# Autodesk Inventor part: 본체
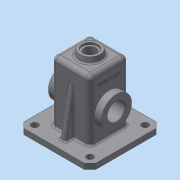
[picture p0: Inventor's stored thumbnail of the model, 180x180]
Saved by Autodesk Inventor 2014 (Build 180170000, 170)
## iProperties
Created: 2016-02
Part Number: 본체
Material: 일반
Document SubType Name: Modeling
Designer: 406-강의용
Density: 1 g/cm^3
Appearance: 기본값
Author: 406-강의용
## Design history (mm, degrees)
sketch "스케치1"
  geometry: L1 (-65, 0)-(65, 0); L2 (65, 0)-(65, 10); L3 (65, 10)-(-65, 10); L4 (-65, 10)-(-65, 0); 2 further points
  constraints: 8 end point, 2 parallel, 1 coincident, 1 horizontal, 1 midpoint, 1 perpendicular
  dimensions: "d0" = 130 distance between parallel lines of L4 L2; "d1" = 10 distance between parallel lines of L1 L3
extrude "돌출1" new body sketch "스케치1" distance "d2" = 130; taper "d3" = 0 deg
sketch "스케치2"
  geometry: L1 (130, 0)-(0, 0) reference; L2 (130, 0)-(130, -130) reference; L3 (30, -100)-(100, -100); L4 (100, -100)-(100, -30); L5 (100, -30)-(30, -30); L6 (30, -30)-(30, -100); 5 further points
  constraints: 8 end point, 4 midpoint, 2 parallel, 1 horizontal, 1 horizontal alignment, 1 perpendicular, 1 vertical alignment
  dimensions: "d4" = 70 distance between parallel lines of L3 L5; "d5" = 70 distance between parallel lines of L6 L4
extrude "돌출2" join sketch "스케치2" distance "d6" = 110; taper "d7" = 0 deg
sketch "스케치3"
  geometry: L1 (35, 35)-(95, 35); L2 (95, 35)-(95, 95); L3 (95, 95)-(35, 95); L4 (35, 95)-(35, 35); L5 (100, 100)-(30, 100) reference; L6 (100, 30)-(100, 100) reference; L7 (30, 30)-(100, 30) reference; 1 further point
  constraints: 8 end point, 2 parallel, 2 perpendicular, 1 horizontal
  dimensions: "d8" = 5 distance between parallel lines of L5 L3; "d9" = 5 distance between parallel lines of L6 L2; "d10" = 5 distance between parallel lines of L7 L1
extrude "돌출3" cut sketch "스케치3" distance "d11" = 115; taper "d12" = 0 deg
fillet "모깎기1" dims "d13" = 8
fillet "모깎기2" dims "d14" = 8
chamfer "모따기1" distance "d15" = 10; stored, may be unused: second distance "d16" = 2, angle "d17" = 45 deg
node "작업 평면1"
sketch "스케치4"
  geometry: L1 (90, 112)-(90, 10) reference; L2 (90, 10)-(120, 10) reference; L3 (120, 10)-(120, 0) reference; L4 (120, 0)-(85, 0) reference; L5 (85, 0)-(85, 115) reference; L6 (85, 115)-(25, 115) reference; L7 (25, 115)-(25, 0) reference; L8 (25, 0)-(-10, 0) reference; L9 (-10, 0)-(-10, 10) reference; L10 (-10, 10)-(20, 10) reference; L11 (20, 10)-(20, 112) reference; L12 (28, 120)-(82, 120) reference; L13 (105, 10)-(90, 95.069); A1 r 8 centre (82, 112) between (90, 112) and (82, 120) reference; A2 r 8 centre (28, 112) between (28, 120) and (20, 112) reference
  constraints: 2 end point, 1 midpoint, 1 point on line
  dimensions: "d18" = 100 deg angle of L2 L13; "d19" = 15 distance from line of L3 L13.start
extrude "돌출4" join sketch "스케치4" stored distance "d20" = 10; taper "d21" = 0 deg
fillet "모깎기3" dims "d22" = 3
fillet "모깎기4" dims "d23" = 3
node "작업 평면2"
fillet "모깎기5" dims "d24" = 3
node "작업 평면3"
sketch "스케치6"
  geometry: L1 (62, 0)-(62, -99) reference; L2 (65, -102)-(92, -102) reference; L3 (92, -102)-(92, -112) reference; L4 (92, -112)-(57, -112) reference; L5 (57, -112)-(57, 3) reference; L6 (57, 3)-(-3, 3) reference; L7 (-3, 3)-(-3, -112) reference; L8 (-3, -112)-(-38, -112) reference; L9 (-38, -112)-(-38, -102) reference; L10 (-38, -102)-(-11, -102) reference; L11 (-8, -99)-(-8, 0) reference; L12 (0, 8)-(54, 8) reference; L13 (50, -57)-(75, -57); L14 (50, -41)-(75, -41); L15 (75, -41)-(75, -29.5); L16 (75, -29.5)-(57, -29.5); L17 (57, -29.5)-(50, -36.5); L18 (50, -36.5)-(50, -41); A1 r 8 centre (54, 0) between (62, 0) and (54, 8) reference; A2 r 3 centre (65, -99) between (62, -99) and (65, -102) reference; A3 r 3 centre (-11, -99) between (-11, -102) and (-8, -99) reference; A4 r 8 centre (0, 0) between (0, 8) and (-8, 0) reference; 1 further point
  constraints: 12 end point, 3 perpendicular, 2 parallel, 2 vertical alignment, 1 point on line
  dimensions: "d30" = 55 distance between parallel lines of L4 L13; "d31" = 7 distance from line of L5 L13.start; "d32" = 25 distance of L13.start L13.end; "d33" = 32 diameter of L14 L13; "d34" = 55 diameter of L16 L13; "d35" = 135 deg angle of L5 L17
revolve "회전1" sketch "스케치6" stored, may be unused: angle "d36" = 90 deg
sketch "스케치7"
  geometry: L1 (62, 0)-(62, -29.5) reference; L2 (62, -29.5)-(75, -29.5) reference; L3 (75, -29.5)-(75, -41) reference; L4 (75, -41)-(62, -41) reference; L5 (62, -41)-(62, -73) reference; L6 (62, -73)-(75, -73) reference; L7 (75, -73)-(75, -84.5) reference; L8 (75, -84.5)-(62, -84.5) reference; L9 (62, -84.5)-(62, -99) reference; L10 (65, -102)-(92, -102) reference; L11 (92, -102)-(92, -112) reference; L12 (92, -112)-(57, -112) reference; L13 (57, -112)-(57, -84.5) reference; L14 (57, -84.5)-(50, -77.5) reference; L15 (50, -77.5)-(50, -73) reference; L16 (50, -73)-(57, -73) reference; L17 (57, -73)-(57, -41) reference; L18 (57, -41)-(50, -41) reference; L19 (50, -41)-(50, -36.5) reference; L20 (50, -36.5)-(57, -29.5) reference; L21 (57, -29.5)-(57, 3) reference; L22 (57, 3)-(-3, 3) reference; L23 (-3, 3)-(-3, -112) reference; L24 (-3, -112)-(-38, -112) reference; L25 (-38, -112)-(-38, -102) reference; L26 (-38, -102)-(-11, -102) reference; L27 (-8, -99)-(-8, 0) reference; L28 (0, 8)-(54, 8) reference; L29 (34.755, -57)-(89.812, -57); L30 (57, -57)-(62, -57); L31 (62, -57)-(62, -41); L32 (62, -41)-(57, -41); L33 (57, -41)-(57, -57); A1 r 8 centre (54, 0) between (62, 0) and (54, 8) reference; A2 r 3 centre (65, -99) between (62, -99) and (65, -102) reference; A3 r 3 centre (-11, -99) between (-11, -102) and (-8, -99) reference; A4 r 8 centre (0, 0) between (0, 8) and (-8, 0) reference; 1 further point
  constraints: 10 end point, 3 parallel, 1 horizontal, 1 midpoint, 1 perpendicular, 1 point on line
  dimensions: "d37" = 55 distance between parallel lines of L12 L29
revolve "회전2" sketch "스케치7" stored, may be unused: angle "d38" = 90 deg
fillet "모깎기8" dims "d39" = 3
fillet "모깎기9" dims "d40" = 3
chamfer "모따기2" distance "d41" = 1; stored, may be unused: second distance "d42" = 2, angle "d43" = 45 deg
fillet "모깎기10" dims "d44" = 0.5
fillet "모깎기11" dims "d45" = 0.5
sketch "스케치8"
  geometry: L1 (112, 30)-(95.332, 30) reference; L2 (94.811, 29.954)-(12.479, 15.437) reference; L3 (10, 12.483)-(10, 0) reference; L4 (10, 0)-(0, 0) reference; L5 (0, 0)-(0, 35) reference; L6 (0, 35)-(112, 35) reference; L7 (115, 38)-(115, 92) reference; L8 (112, 95)-(0, 95) reference; L9 (0, 95)-(0, 130) reference; L10 (0, 130)-(10, 130) reference; L11 (10, 130)-(10, 117.517) reference; L12 (12.479, 114.563)-(94.811, 100.046) reference; L13 (95.332, 100)-(112, 100) reference; L14 (120, 92)-(120, 38) reference; L15 (120, 65)-(130, 65); L16 (120, 45)-(130, 46.763); L17 (130, 46.763)-(130, 65); A1 r 3 centre (95.332, 27) between (95.332, 30) and (94.811, 29.954) reference; A2 r 3 centre (13, 12.483) between (12.479, 15.437) and (10, 12.483) reference; A3 r 3 centre (112, 38) between (112, 35) and (115, 38) reference; A4 r 3 centre (112, 92) between (115, 92) and (112, 95) reference; A5 r 3 centre (13, 117.517) between (10, 117.517) and (12.479, 114.563) reference; A6 r 3 centre (95.332, 103) between (94.811, 100.046) and (95.332, 100) reference; A7 r 8 centre (112, 92) between (120, 92) and (112, 100) reference; A8 r 8 centre (112, 38) between (112, 30) and (120, 38) reference
  constraints: 6 end point, 2 perpendicular, 1 midpoint, 1 parallel, 1 point on line
  dimensions: "d46" = 10 distance of L15.start L15.end; "d47" = 10 deg angle of L1 L16 (derived); "d48" = 40 diameter of L16.start L15
revolve "회전3" sketch "스케치8" stored, may be unused: angle "d49" = 90 deg
sketch "스케치9"
  geometry: C1 r 18.237 at (0, 0) reference; 1 further point
hole "구멍1" sketch "스케치9" at (0, 0) diameter "d50" = 21; stored, may be unused: countersink angle "d54" = 90 deg, drill point angle "d56" = 118 deg; dims "d51" = 6, "d52" = 28, "d53" = 4, "d55" = 8
fillet "모깎기12" dims "d57" = 3
sketch "스케치10"
  geometry: L1 (120, -10)-(120, -120) reference; L2 (110, 0)-(0, 0) reference; C1 r 6 at (105, -115); C2 r 6 at (105, -15); 1 further point
  constraints: 2 centre point, 1 vertical alignment
  dimensions: "d58" = 6 radius of C1; "d59" = 6 radius of C2; "d60" = 15 distance from line of L2 C2.centre; "d61" = 100 distance of C1.centre C2.centre; "d62" = 15 distance from line of L1 C2.centre
extrude "돌출5" cut sketch "스케치10" distance "d63" = 33; taper "d64" = 0 deg
sketch "스케치11"
  geometry: L1 (62, -99)-(62, 0) reference; L2 (8.763, 18)-(45.237, 18) reference; 2 further points
  constraints: 1 other
  dimensions: "d68" = 35 distance from line of L1 point (27, -12); "d69" = 30 distance from line of L2 point (27, -12)
feature "엠보싱1" sketch "스케치11" dims "d70" = 0.5, "d71" = 0
node "솔리드1"
mirror "대칭1"
mirror "대칭2"
mirror "대칭3"
mirror "대칭4"
pattern_linear "직사각형 패턴1" dims "d67" = 100
node "절단 모서리 투영1"
node "절단 모서리 투영3"
node "절단 모서리 투영4"
node "절단 모서리 투영5"
